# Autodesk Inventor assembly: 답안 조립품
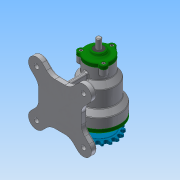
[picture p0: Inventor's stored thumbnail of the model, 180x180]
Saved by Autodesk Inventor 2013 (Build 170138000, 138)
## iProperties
Created: 2017-03
Part Number: 답안 조립품
Document SubType Name: Assembly
Designer: Administrator
Author: Administrator
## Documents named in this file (14)
- C:\Users\Administrator\Desktop\470308V1003\답안 조립품.iam
- C:\Users\Administrator\Desktop\470308V1003\본체.ipt
- C:\Users\Administrator\Desktop\470308V1003\뒤커버.ipt
- C:\Users\Administrator\Desktop\470308V1003\베어링-6200.ipt
- C:\Users\Administrator\Desktop\470308V1003\베어링-6203.ipt
- C:\Users\Administrator\Desktop\470308V1003\볼트 M4 x 12.ipt
- C:\Users\Administrator\Desktop\470308V1003\볼트 M5 x 10.ipt
- 볼트 M5 x 10.ipt
- C:\Users\Administrator\Desktop\470308V1003\스프로킷.ipt
- C:\Users\Administrator\Desktop\470308V1003\앞커버.ipt
- C:\Users\Administrator\Desktop\470308V1003\오일 실 10 20 7.ipt
- C:\Users\Administrator\Desktop\470308V1003\오일 실 17 30 8.ipt
- C:\Users\Administrator\Desktop\470308V1003\축.ipt
- C:\Users\Administrator\Desktop\470308V1003\키5x5.ipt
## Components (9 placed, 1 different names)
1. ISO 4762 M4 x 12:1
2. ISO 4762 M4 x 12:3
3. ISO 4762 M4 x 12:4
4. ISO 4762 M4 x 12:2
5. ISO 4762 M4 x 12:5
6. ISO 4762 M4 x 12:6
7. ISO 4762 M4 x 12:7
8. ISO 4762 M4 x 12:8
9. ISO 4762 M4 x 12:9
